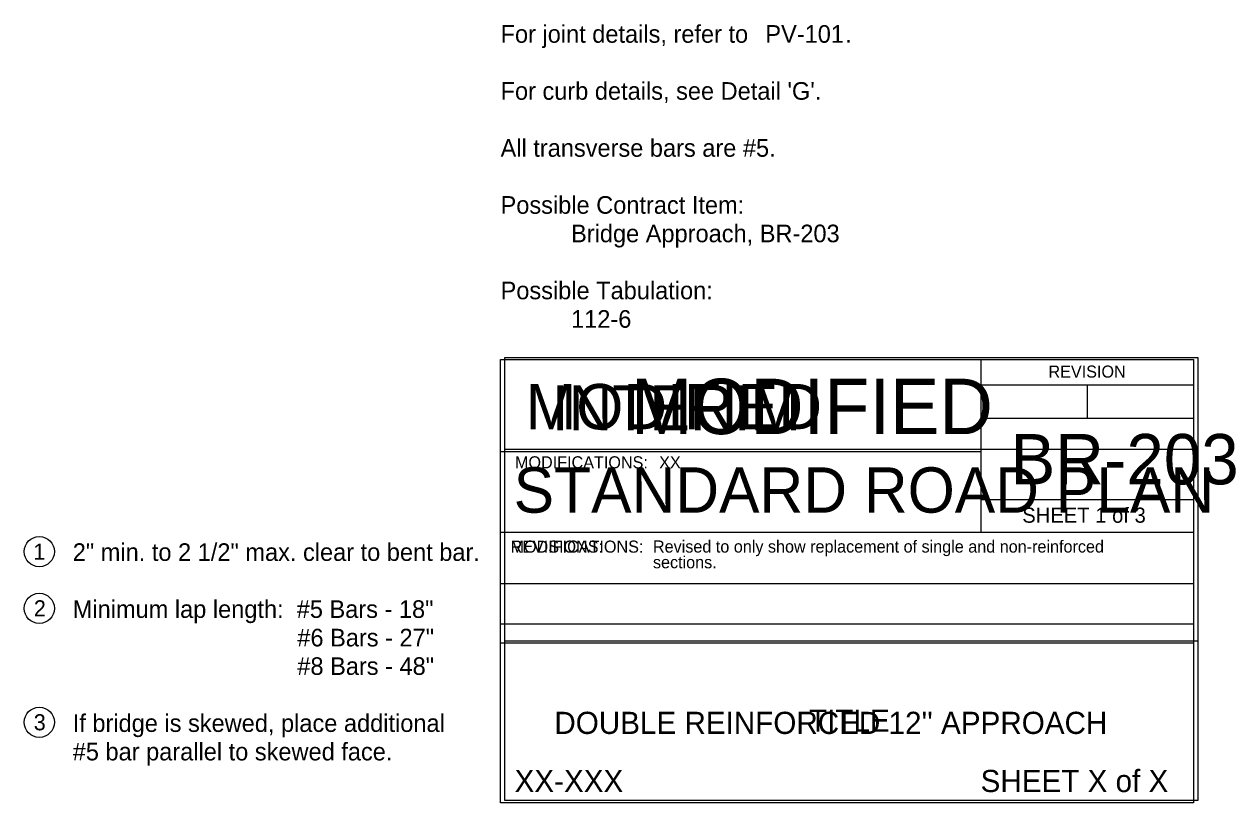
# Model space of a CAD drawing. Extents: x -2134860 to -2124557, y -2139046 to -2137324.
# Drawn here: x -2132960 to -2131757, y -2139046 to -2138273 of the extents above; entities that cross this region are included whole.
import ezdxf

# ---------------------------------------------------------------- set-up
doc = ezdxf.new("R2010")
doc.units = 0
for name, color, linetype in [('Barrier', 7, 'Continuous'), ('BridgeSuperStructureExisting', 7, 'Continuous'), ('Dimension', 7, 'Continuous'), ('dsnAlignmentCurveData', 7, 'Continuous'), ('dsnAlignmentTic', 7, 'Continuous'), ('DsnShtInsideBorder', 7, 'Continuous'), ('DsnShtPlotIdentification', 7, 'Continuous')]:
    doc.layers.add(name, color=color, linetype=linetype)

msp = doc.modelspace()

# ---------------------------------------------------------------- linework, layer by layer
at = {"layer": 'BridgeSuperStructureExisting'}
for centre in [(-2132945.4, -2138796.6), (-2132945.4, -2138852.9), (-2132945.4, -2138966)]:
    msp.add_circle(centre, 15, dxfattribs=at)
at = {"layer": 'Dimension'}
for p, q in [((-2132010.4, -2138605.9), (-2132010.4, -2138697.3)), ((-2132010.4, -2138630.9), (-2131799.4, -2138630.9)), ((-2131904.9, -2138630.9), (-2131904.9, -2138664.1)), ((-2132010.4, -2138664.1), (-2131799.4, -2138664.1)), ((-2132487.5, -2138697.3), (-2132010.4, -2138697.3)), ((-2132010.4, -2138697.3), (-2132010.4, -2138777.3)), ((-2131799.4, -2138745.1), (-2132010.4, -2138745.1)), ((-2132487.5, -2138777.3), (-2131799.4, -2138777.3)), ((-2132487.5, -2138828.3), (-2131799.4, -2138828.3)), ((-2132487.5, -2138868.3), (-2131799.4, -2138868.3)), ((-2132487.5, -2138887.3), (-2131799.4, -2138887.3))]:
    msp.add_line(p, q, dxfattribs=at)
msp.add_lwpolyline([(-2132487.5, -2138605.9), (-2131799.4, -2138605.9), (-2131799.4, -2139045.9), (-2132487.5, -2139045.9)], close=True, dxfattribs=at)
at = {"layer": 'DsnShtInsideBorder'}
for p, q in [((-2132483.1, -2138695), (-2131795.1, -2138695)), ((-2132483.1, -2138885), (-2131795.1, -2138885))]:
    msp.add_line(p, q, dxfattribs=at)
msp.add_lwpolyline([(-2132483.1, -2138603.7), (-2131795.1, -2138603.7), (-2131795.1, -2139043.7), (-2132483.1, -2139043.7)], close=True, dxfattribs=at)

# ---------------------------------------------------------------- texts
at = {"layer": 'Barrier'}
for s, p in [('For joint details, refer to ', (-2132487.4, -2138291.3)), ('PV-101', (-2132224.5, -2138291.3)), ('PV-101', (-2132224.5, -2138291.3)), ('.', (-2132145.2, -2138291.3)), ("For curb details, see Detail 'G'.", (-2132487.4, -2138347.9)), ('All transverse bars are #5.', (-2132487.4, -2138404.5)), ('Possible Contract Item:', (-2132487.4, -2138461.1)), ('Bridge Approach, BR-203', (-2132417.4, -2138489.4)), ('Possible Tabulation:', (-2132487.4, -2138546)), ('112-6', (-2132417.4, -2138574.3)), ('112-6', (-2132417.4, -2138574.3)), ('2" min. to 2 1/2" max. clear to bent bar.', (-2132912.2, -2138805.8)), ('Minimum lap length:  #5 Bars - 18"', (-2132912.2, -2138862.4)), ('  #6 Bars - 27"', (-2132702.2, -2138890.7)), ('  #8 Bars - 48"', (-2132702.2, -2138919)), ('If bridge is skewed, place additional', (-2132912.2, -2138975.6)), ('#5 bar parallel to skewed face.', (-2132912.2, -2139003.9))]:
    msp.add_text(s, height=17.5, dxfattribs=at).set_placement(p)
at = {"layer": 'BridgeSuperStructureExisting'}
for s, p in [('1', (-2132951.4, -2138804.6)), ('2', (-2132950.8, -2138860.9)), ('3', (-2132950.9, -2138974))]:
    msp.add_text(s, height=16, dxfattribs=at).set_placement(p)
at = {"layer": 'Dimension'}
for s, height, p in [('REVISION', 12, (-2131943.4, -2138623.8)), ('BR-203', 50, (-2131981.2, -2138729.8)), ('STANDARD ROAD PLAN', 45.001, (-2132474.4, -2138757.9)), ('SHEET 1 of 3', 15, (-2131969.4, -2138767.9)), ('Revised to only show replacement of single and non-reinforced', 12, (-2132336.1, -2138797.5)), ('sections.', 12, (-2132336.1, -2138813.1)), ("DOUBLE REINFORCED 12'' APPROACH", 22, (-2132434, -2138977.6))]:
    msp.add_text(s, height=height, dxfattribs=at).set_placement(p)
at = {"layer": 'dsnAlignmentCurveData'}
msp.add_text('REVISIONS:', height=12, dxfattribs=at).set_placement((-2132477.5, -2138797.6))
at = {"layer": 'dsnAlignmentTic'}
for s, height, p in [('MODIFIED', 45, (-2132462.4, -2138675.1)), ('MODIFICATIONS:', 12, (-2132477.5, -2138797.6))]:
    msp.add_text(s, height=height, dxfattribs=at).set_placement(p)
at = {"layer": 'DsnShtInsideBorder'}
for s, height, p in [('MODIFIED', 55, (-2132358.1, -2138679.9)), ('MODIFICATIONS:', 12, (-2132473.1, -2138713.9)), ('XX', 12, (-2132329.9, -2138713.9)), ('TITLE', 22, (-2132181.1, -2138975.4)), ('XX-XXX', 22, (-2132473.5, -2139035.3)), ('SHEET X of X', 22, (-2132010.8, -2139035.3))]:
    msp.add_text(s, height=height, dxfattribs=at).set_placement(p)
at = {"layer": 'DsnShtPlotIdentification'}
msp.add_text('INTERIM', height=45, dxfattribs=at).set_placement((-2132436.5, -2138676.3))

doc.saveas('drawing.dxf')
